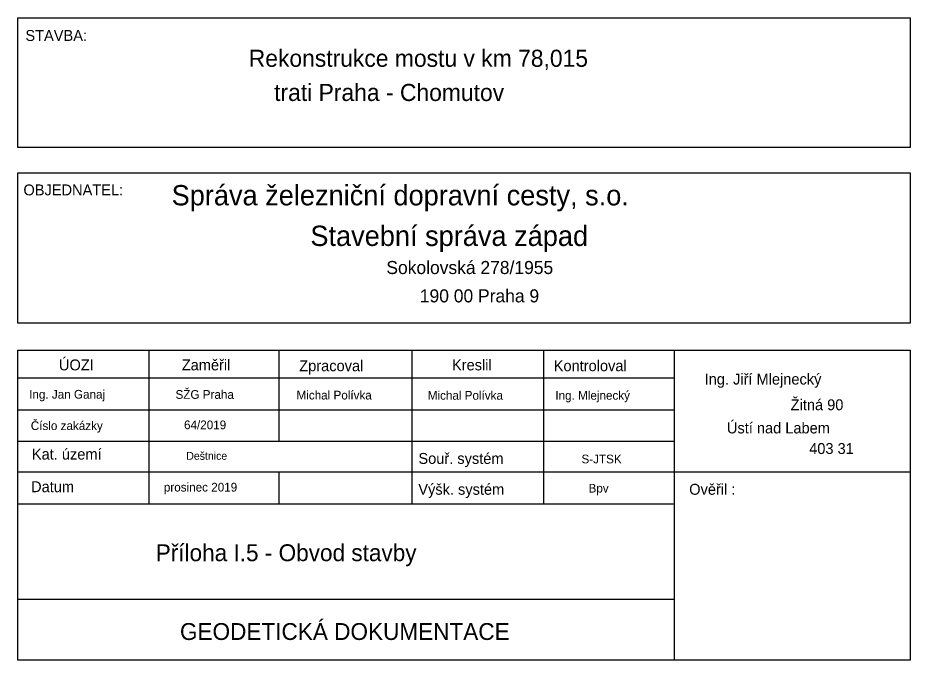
# Model space of a CAD drawing. Extents: x -879530 to -879371, y -1019242 to -1019127.
import ezdxf

# ---------------------------------------------------------------- set-up
doc = ezdxf.new("R2010")
doc.units = 0
doc.layers.add('LEGENDA', color=7, linetype='Continuous')
doc.layers.add('tabulka', color=7, linetype='Continuous')

msp = doc.modelspace()

# ---------------------------------------------------------------- linework, layer by layer
at = {"layer": 'tabulka'}
for p, q in [((-879530.09, -1019186.45), (-879371.44, -1019186.45)), ((-879506.8, -1019186.45), (-879506.8, -1019213.77)), ((-879483.66, -1019186.45), (-879483.66, -1019202.65)), ((-879460.06, -1019186.45), (-879460.06, -1019213.77)), ((-879436.61, -1019186.45), (-879436.61, -1019213.77)), ((-879413.31, -1019241.58), (-879413.31, -1019186.45)), ((-879530.09, -1019191.36), (-879413.31, -1019191.36)), ((-879530.09, -1019197.07), (-879413.31, -1019197.07)), ((-879530.09, -1019202.65), (-879413.31, -1019202.65)), ((-879530.09, -1019208.07), (-879371.44, -1019208.07)), ((-879483.66, -1019208.07), (-879483.66, -1019213.77)), ((-879530.09, -1019213.77), (-879413.31, -1019213.77)), ((-879530.09, -1019230.76), (-879413.31, -1019230.76))]:
    msp.add_line(p, q, dxfattribs=at)
for points in [[(-879530.09, -1019127.36), (-879371.44, -1019127.36), (-879371.44, -1019150.43), (-879530.09, -1019150.43)], [(-879530.09, -1019154.95), (-879371.44, -1019154.95), (-879371.44, -1019181.64), (-879530.09, -1019181.64)]]:
    msp.add_lwpolyline(points, close=True, dxfattribs=at)
msp.add_lwpolyline([(-879371.44, -1019186.45), (-879371.44, -1019241.58), (-879530.09, -1019241.58), (-879530.09, -1019186.45)], dxfattribs=at)

# ---------------------------------------------------------------- texts
at = {"layer": 'LEGENDA'}
for s, p in [('Rekonstrukce mostu v km 78,015 ', (-879489.04, -1019136.07)), ('    trati Praha - Chomutov', (-879489.04, -1019142.15))]:
    msp.add_text(s, height=3.04, dxfattribs=at).set_placement(p)
at = {"layer": 'tabulka'}
for s, height, p in [('STAVBA:', 1.94, (-879528.75, -1019131.47)), ('OBJEDNATEL:', 1.94, (-879529.1, -1019158.93)), ('Správa železniční dopravní cesty, s.o.', 3.61, (-879502.75, -1019160.71)), ('Stavební správa západ', 3.61, (-879478.08, -1019167.93)), ('Sokolovská 278/1955', 2.32, (-879464.57, -1019172.92)), ('190 00 Praha 9', 2.32, (-879458.62, -1019177.96)), ('ÚOZI', 1.94, (-879522.79, -1019190.05)), ('Zaměřil', 1.94, (-879500.95, -1019190.05)), ('Zpracoval', 1.94, (-879480.06, -1019190.2)), ('Kreslil', 1.94, (-879452.9, -1019190.05)), ('Kontroloval', 1.94, (-879434.81, -1019190.2)), ('Ing. Jiří Mlejnecký', 1.94, (-879407.98, -1019192.57)), ('Ing. Jan Ganaj', 1.552, (-879528.08, -1019195.08)), ('SŽG Praha', 1.552, (-879502.06, -1019195.11)), ('Michal Polívka', 1.552, (-879480.54, -1019195.23)), ('Michal Polívka', 1.552, (-879457.21, -1019195.27)), ('Ing. Mlejnecký', 1.552, (-879434.52, -1019195.27)), ('Žitná 90', 1.94, (-879392.68, -1019197.14)), ('Číslo zakázky', 1.552, (-879527.79, -1019200.66)), ('64/2019', 1.552, (-879500.55, -1019200.52)), ('Ústí nad Labem', 1.94, (-879404.02, -1019201.26)), ('403 31', 1.94, (-879389.39, -1019204.92)), ('Kat. území', 1.94, (-879527.6, -1019205.91)), ('Deštnice', 1.397, (-879500.14, -1019205.95)), ('Souř. systém', 1.94, (-879458.87, -1019206.68)), ('S-JTSK', 1.552, (-879429.88, -1019206.59)), ('Datum', 1.94, (-879527.74, -1019211.71)), ('prosinec 2019', 1.552, (-879504.13, -1019211.6)), ('Výšk. systém', 1.94, (-879458.89, -1019212.17)), ('Bpv', 1.552, (-879428.62, -1019211.78)), ('Ověřil :', 1.94, (-879410.72, -1019212.17)), ('Příloha I.5 - Obvod stavby', 3, (-879505.58, -1019223.98)), ('GEODETICKÁ DOKUMENTACE ', 3, (-879501.27, -1019237.99))]:
    msp.add_text(s, height=height, dxfattribs=at).set_placement(p)

doc.saveas('drawing.dxf')
